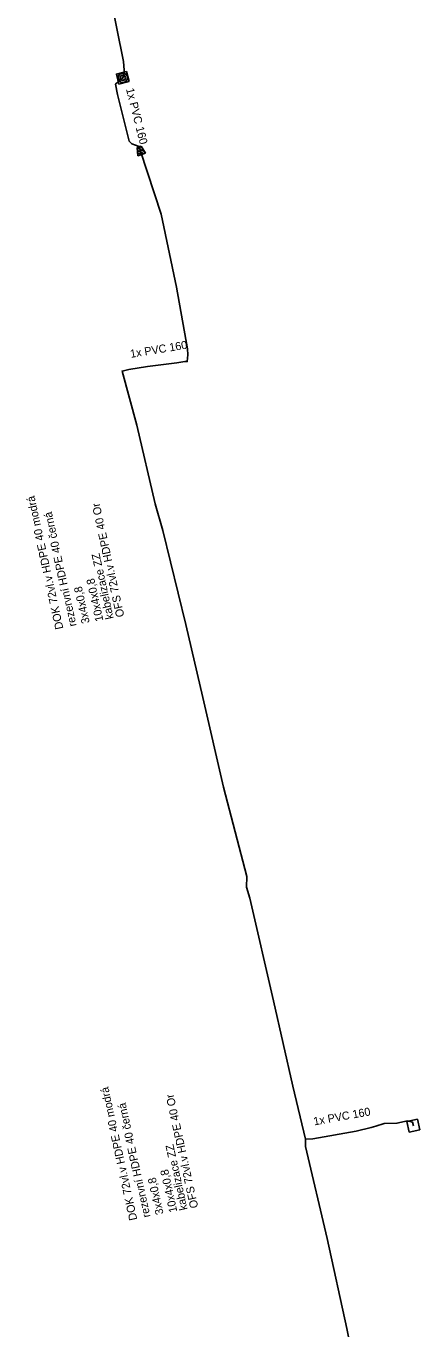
# Model space of a CAD drawing. Extents: x -702379 to -702256, y -1022496 to -1021998.
# Drawn here: x -702328.6 to -702255.6, y -1022495.6 to -1022252.3 of the extents above; entities that cross this region are included whole.
import ezdxf

# ---------------------------------------------------------------- set-up
doc = ezdxf.new("R2010")
doc.units = 0
for name, color, linetype in [('Vrstva 1', 7, 'Continuous'), ('Vrstva 32', 7, 'Continuous'), ('Vrstva 33', 7, 'Continuous'), ('Vrstva 35', 7, 'Continuous'), ('Vrstva 47', 7, 'Continuous')]:
    doc.layers.add(name, color=color, linetype=linetype)

msp = doc.modelspace()

# ---------------------------------------------------------------- linework, layer by layer
at = {"layer": 'Vrstva 1'}
for points in [[(-702276.82, -1022458.9), (-702279.16, -1022449.05), (-702282.76, -1022433.22), (-702287.16, -1022414.14), (-702287.76, -1022412.11), (-702287.72, -1022410.12), (-702292.02, -1022393.55), (-702295.9, -1022376.89), (-702299.03, -1022363.35), (-702303.28, -1022345.92), (-702304.75, -1022340.95), (-702308.13, -1022326.37), (-702310.85, -1022316.33), (-702309.6, -1022316.01), (-702306.12, -1022315.44), (-702300.69, -1022314.76), (-702299.24, -1022314.53), (-702298.76, -1022314.55), (-702298.69, -1022313.33), (-702298.72, -1022312.21), (-702300.78, -1022300.76), (-702303.58, -1022287.18), (-702307.43, -1022275.48), (-702307.7, -1022274.65), (-702309.02, -1022274.12), (-702309.54, -1022273.66), (-702311.73, -1022264.96), (-702312.06, -1022263.05), (-702310.73, -1022261.87), (-702310.49, -1022261.16), (-702310.49, -1022260.44), (-702310.61, -1022258.86), (-702311.82, -1022252.7), (-702313.72, -1022243.1)], [(-702276.82, -1022458.9), (-702275.48, -1022458.83), (-702267.45, -1022457.39), (-702264.65, -1022456.74), (-702263.76, -1022456.47), (-702262.27, -1022455.96), (-702259.89, -1022455.93), (-702257.91, -1022455.51), (-702257.4, -1022455.59), (-702256.98, -1022455.73), (-702256.83, -1022456.41)], [(-702268.83, -1022495.58), (-702269.18, -1022494.03), (-702272.82, -1022477.32), (-702276.84, -1022460.25), (-702276.82, -1022458.9)]]:
    msp.add_lwpolyline(points, dxfattribs=at)
at = {"layer": 'Vrstva 32'}
for p, q in [((-702307.33, -1022274.56), (-702308.04, -1022274.8)), ((-702307.58, -1022274.65), (-702307.13, -1022274.87)), ((-702306.5, -1022275.88), (-702307.33, -1022274.56)), ((-702308.04, -1022274.8), (-702307.93, -1022276.35)), ((-702308.04, -1022274.87), (-702306.71, -1022275.54)), ((-702308.01, -1022275.34), (-702306.76, -1022275.96)), ((-702307.97, -1022275.8), (-702307.3, -1022276.14)), ((-702307.94, -1022276.27), (-702307.84, -1022276.32)), ((-702307.93, -1022276.35), (-702306.5, -1022275.88))]:
    msp.add_line(p, q, dxfattribs=at)
msp.add_lwpolyline([(-702310.73, -1022261.87), (-702312.06, -1022263.05), (-702311.73, -1022264.96), (-702309.54, -1022273.66), (-702309.02, -1022274.12), (-702307.7, -1022274.65)], dxfattribs=at)
msp.add_circle((-702310.73, -1022261.87), 0.5, dxfattribs=at)
at = {"layer": 'Vrstva 33'}
msp.add_lwpolyline([(-702309.57, -1022262.57), (-702310.04, -1022260.71), (-702311.9, -1022261.18), (-702311.43, -1022263.04)], close=True, dxfattribs=at)
msp.add_circle((-702310.73, -1022261.87), 0.864, dxfattribs=at)
at = {"layer": 'Vrstva 35'}
for points in [[(-702310.73, -1022261.87), (-702312.06, -1022263.05), (-702311.73, -1022264.96), (-702309.54, -1022273.66), (-702309.02, -1022274.12), (-702307.7, -1022274.65)], [(-702310.85, -1022316.33), (-702309.6, -1022316.01), (-702306.12, -1022315.44), (-702300.69, -1022314.76), (-702299.24, -1022314.53), (-702298.76, -1022314.55)], [(-702276.82, -1022458.9), (-702275.48, -1022458.83), (-702267.45, -1022457.39), (-702264.65, -1022456.74)]]:
    msp.add_lwpolyline(points, dxfattribs=at)
at = {"layer": 'Vrstva 47'}
msp.add_lwpolyline([(-702257.59, -1022457.6), (-702258.03, -1022455.65), (-702256.08, -1022455.21), (-702255.64, -1022457.16), (-702257.59, -1022457.6)], dxfattribs=at)

# ---------------------------------------------------------------- texts
at = {"layer": 'Vrstva 32'}
for s, height, rotation, p in [('M', 0.6, 259.7988, (-702310.97, -1022261.49)), ('DOK 72vl.v HDPE 40 modrá', 1.5, 102.3096, (-702321.74, -1022364.1)), ('rezervní HDPE 40 černá', 1.5, 102.3096, (-702319.29, -1022363.57)), ('OFS 72vl.v HDPE 40 Or', 1.5, 102.3096, (-702310.43, -1022361.83)), ('kabelizace ZZ', 1.5, 102.3096, (-702312.41, -1022362.21)), ('10x4x0,8', 1.5, 102.3096, (-702314.31, -1022362.63)), ('3x4x0,8', 1.5, 102.3096, (-702316.85, -1022363.03)), ('DOK 72vl.v HDPE 40 modrá', 1.5, 102.3096, (-702308.03, -1022473.82)), ('rezervní HDPE 40 černá', 1.5, 102.3096, (-702305.59, -1022473.28)), ('OFS 72vl.v HDPE 40 Or', 1.5, 102.3096, (-702296.72, -1022471.55)), ('kabelizace ZZ', 1.5, 102.3096, (-702298.7, -1022471.93)), ('10x4x0,8', 1.5, 102.3096, (-702300.6, -1022472.34)), ('3x4x0,8', 1.5, 102.3096, (-702303.15, -1022472.75))]:
    msp.add_text(s, height=height, rotation=rotation, dxfattribs=at).set_placement(p)
at = {"layer": 'Vrstva 35'}
for rotation, p in [(284.1308, (-702310.14, -1022263.97)), (9.2968, (-702309.24, -1022313.87)), (10.1842, (-702275.22, -1022456.35))]:
    msp.add_text('1x PVC 160', height=1.5, rotation=rotation, dxfattribs=at).set_placement(p)

doc.saveas('drawing.dxf')
